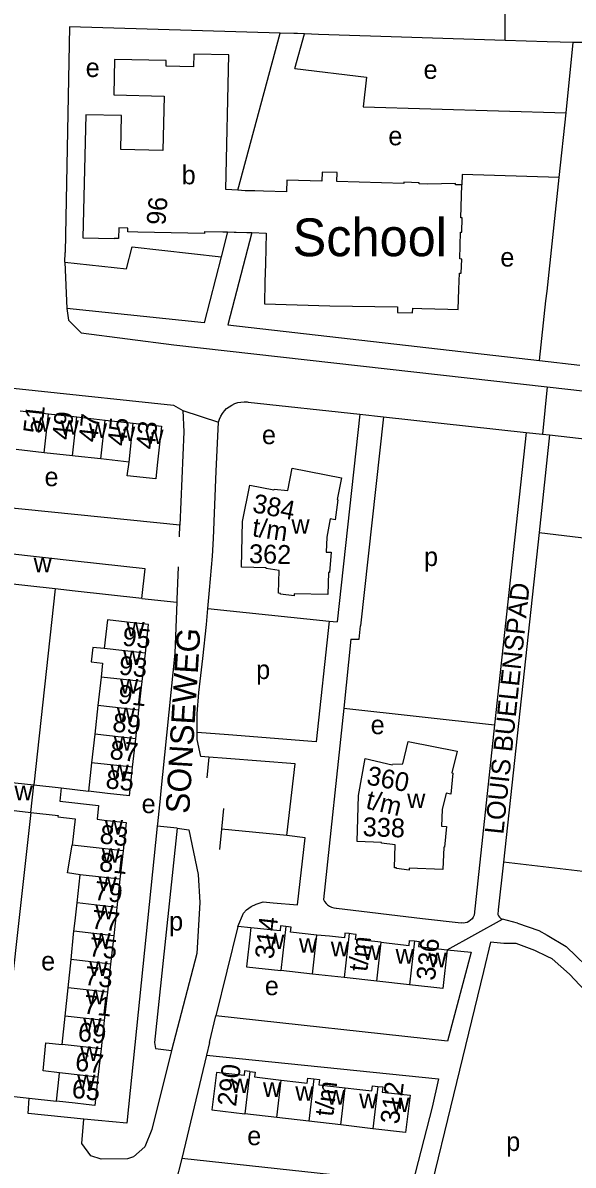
# Model space of a CAD drawing. Extents: x 161936 to 163647, y 386450 to 388633.
# Drawn here: x 162488.9 to 162605.5, y 387951 to 388193.1 of the extents above; entities that cross this region are included whole.
import ezdxf

# ---------------------------------------------------------------- set-up
doc = ezdxf.new("R2010")
doc.units = 0
for name, color, linetype in [('BLT_Basislijn', 7, 'Continuous'), ('BLT_Bebouwing', 7, 'Continuous'), ('BLT_Bebouwing_beschrifting', 7, 'Continuous'), ('BLT_Centroide', 7, 'Continuous'), ('BLT_Huisnummer', 7, 'Continuous'), ('BLT_Huisnummer_ tussenligend', 7, 'Continuous'), ('BLT_Huisnummer_reeks', 7, 'Continuous'), ('BLT_Onderverdeling_panden', 7, 'Continuous'), ('BLT_Straatnaam', 7, 'Continuous'), ('BLT_Straatnaam_verkleind', 7, 'Continuous'), ('BLT_Vlakafsluiter', 7, 'Continuous')]:
    doc.layers.add(name, color=color, linetype=linetype)

msp = doc.modelspace()

# ---------------------------------------------------------------- linework, layer by layer
at = {"layer": 'BLT_Basislijn'}
for p, q in [((162591.14, 388189.38), (162591.12, 388195.74)), ((162534.5, 388157.64), (162543.44, 388190.92)), ((162546.6, 388183.4), (162548.58, 388190.76)), ((162609.32, 388188.96), (162605.52, 388188.92)), ((162497.85, 388142.38), (162497.93, 388144.44)), ((162497.85, 388142.38), (162498.24, 388132.55)), ((162598.44, 388121.53), (162599.78, 388134.16)), ((162598.44, 388121.53), (162606.98, 388120.56)), ((162536.69, 388112.74), (162560.36, 388110.16)), ((162560.36, 388110.16), (162555.53, 388066.15)), ((162560.36, 388110.16), (162565.33, 388109.61)), ((162565.33, 388109.61), (162560.46, 388065.31)), ((162565.33, 388109.61), (162595.57, 388106.3)), ((162595.57, 388106.3), (162588.88, 388044.33)), ((162595.57, 388106.3), (162599.03, 388105.93)), ((162600.54, 388105.76), (162598.32, 388085.1)), ((162599.03, 388105.93), (162600.54, 388105.76)), ((162600.54, 388105.76), (162636.56, 388101.7)), ((162522.13, 388084.21), (162522.22, 388086.64)), ((162598.32, 388085.1), (162590.77, 388015.27)), ((162495.79, 388073.14), (162491.26, 388031.64)), ((162514.13, 388071.09), (162521.54, 388070.34)), ((162528.14, 388069), (162553.83, 388066.33)), ((162553.83, 388066.33), (162551.1, 388040.74)), ((162553.83, 388066.33), (162555.53, 388066.15)), ((162558.46, 388062.52), (162556.92, 388047.89)), ((162556.92, 388047.89), (162552.66, 388007.31)), ((162556.92, 388047.89), (162588.88, 388044.33)), ((162588.88, 388044.33), (162584.53, 388003.99)), ((162497.05, 388030.99), (162502.82, 388030.26)), ((162490.61, 388025.79), (162483.95, 387965.94)), ((162521.63, 388022.41), (162517.4, 388022.89)), ((162590.77, 388015.27), (162589.68, 388005.16)), ((162593.73, 388002.33), (162590.59, 388003.13)), ((162534.52, 388001.6), (162529.82, 387982.7)), ((162537.22, 388001.34), (162534.52, 388001.6)), ((162528.49, 387976.99), (162529.82, 387982.7)), ((162528.49, 387976.99), (162527.86, 387974.33)), ((162527.86, 387974.33), (162522.59, 387952.41)), ((162483.95, 387965.94), (162490.26, 387965.22)), ((162490.26, 387965.22), (162496.06, 387964.57)), ((162522.59, 387952.41), (162521.25, 387947.22))]:
    msp.add_line(p, q, dxfattribs=at)
for points in [[(162543.44, 388190.92), (162498.79, 388192.23), (162497.93, 388144.44)], [(162546.33, 388190.83), (162543.44, 388190.92)], [(162548.58, 388190.76), (162547.12, 388190.81), (162546.33, 388190.83)], [(162591.14, 388189.38), (162551.58, 388190.66), (162548.58, 388190.76)], [(162605.52, 388188.92), (162600, 388189.1), (162591.14, 388189.38)], [(162604.07, 388174.05), (162605.52, 388188.92)], [(162546.6, 388183.4), (162561.76, 388181.57), (162561.03, 388175.31), (162604.07, 388174.05)], [(162602.6, 388160.36), (162604.07, 388174.05)], [(162602.6, 388160.36), (162581.99, 388160.96), (162581.93, 388158.74)], [(162599.78, 388134.16), (162600, 388136.23), (162602.6, 388160.36)], [(162532.32, 388148.78), (162530.96, 388143.54)], [(162537.45, 388148.64), (162532.37, 388129.08)], [(162497.85, 388142.38), (162510.93, 388140.97), (162512.07, 388145.61), (162530.96, 388143.54)], [(162530.96, 388143.54), (162527.32, 388129.53)], [(162498.24, 388132.55), (162498.63, 388130.09), (162501.31, 388127.39), (162520.91, 388124.84), (162600, 388115.94)], [(162527.32, 388129.53), (162498.24, 388132.55)], [(162532.37, 388129.08), (162598.44, 388121.53)], [(162462.15, 388118.33), (162520.89, 388112.08), (162522.8, 388110.92)], [(162600, 388115.94), (162638.7, 388111.58), (162641.05, 388111.51), (162643.08, 388111.89), (162644.73, 388113.96), (162645.02, 388116.24)], [(162522.8, 388110.92), (162523.03, 388106.43), (162522.22, 388086.64)], [(162530.39, 388108.48), (162530.59, 388109.13), (162530.87, 388109.74), (162531.22, 388110.32), (162531.64, 388110.86), (162532.12, 388111.34), (162532.65, 388111.76), (162533.22, 388112.11), (162533.84, 388112.4), (162534.48, 388112.61), (162535.15, 388112.74), (162535.82, 388112.79), (162536.49, 388112.77), (162536.69, 388112.74)], [(162529.36, 388083.81), (162529.88, 388098.09), (162530.39, 388108.48)], [(162593.73, 388002.33), (162598.24, 388000.78), (162600, 387999.74), (162604.06, 387997.34), (162622.92, 387979.16), (162624.11, 387982.32), (162636.56, 388101.7)], [(162522.22, 388086.64), (162472.61, 388091.7), (162471.95, 388091.77)], [(162598.32, 388085.1), (162629.52, 388081.37), (162622.01, 388011.53), (162590.77, 388015.27)], [(162528.14, 388069), (162528.49, 388072.86), (162529.09, 388080.1), (162529.36, 388083.81)], [(162521.84, 388077.85), (162521.56, 388070.88), (162521.54, 388070.34)], [(162521.54, 388070.34), (162521.12, 388059.5), (162518.13, 388029.66), (162518.03, 388028.71)], [(162525.88, 388042.72), (162525.85, 388046.69), (162526.23, 388051.18), (162527.07, 388058.4), (162527.82, 388065.62), (162528.14, 388069)], [(162558.46, 388062.52), (162560.19, 388062.52), (162560.46, 388065.31)], [(162528.36, 388037.51), (162526.64, 388037.64), (162525.89, 388041.25), (162525.88, 388042.72)], [(162551.1, 388040.74), (162532.51, 388042.2), (162525.88, 388042.72)], [(162528.36, 388037.51), (162527.92, 388033.09)], [(162546.62, 388036.08), (162532.12, 388037.21), (162528.36, 388037.51)], [(162544.87, 388020.86), (162546.62, 388036.08)], [(162518.03, 388028.71), (162517.45, 388023.38), (162517.4, 388022.89)], [(162531.45, 388026.6), (162531.45, 388026.6), (162531.01, 388022.26)], [(162517.4, 388022.89), (162510.98, 387959.96), (162501.87, 387960.77)], [(162521.63, 388022.41), (162516.82, 387977.05), (162517.01, 387975.72), (162520.43, 387975.31)], [(162521.63, 388022.41), (162524.1, 388022.12), (162526.09, 388012.62), (162526.46, 388006.67), (162525.82, 387995.91), (162520.43, 387975.31)], [(162531.01, 388022.26), (162531.01, 388022.26), (162530.57, 388017.92)], [(162544.87, 388020.86), (162531.01, 388022.26)], [(162534.52, 388001.6), (162535.67, 388004.45), (162536.33, 388005.15), (162537.3, 388005.83), (162538.35, 388006.33), (162539.88, 388006.81), (162541.95, 388006.65), (162547.15, 388006.18), (162548.78, 388020.41), (162544.87, 388020.86)], [(162552.66, 388007.31), (162552.88, 388006.88), (162553.17, 388006.49), (162553.52, 388006.16), (162553.91, 388005.89), (162554.35, 388005.69), (162554.82, 388005.56), (162555.3, 388005.51), (162555.42, 388005.51)], [(162555.42, 388005.51), (162573.64, 388003.3), (162581.82, 388002.36)], [(162589.68, 388005.16), (162589.6, 388004.16), (162589.72, 388003.84), (162589.92, 388003.56), (162590.18, 388003.33), (162590.48, 388003.17), (162590.59, 388003.13)], [(162584.53, 388003.99), (162584.36, 388003.59), (162584.11, 388003.22), (162583.81, 388002.91), (162583.45, 388002.65), (162583.06, 388002.47), (162582.63, 388002.36), (162582.2, 388002.33), (162581.82, 388002.36)], [(162611.3, 387984.51), (162604.76, 387991.48), (162601.11, 387994.73), (162600, 387995.27), (162597.43, 387996.52), (162593.47, 387997.98), (162590.82, 387998), (162588.04, 387998.3), (162586.55, 387992.05), (162568.7, 387918.58), (162570.36, 387917.56), (162582.35, 387916.2)], [(162578.86, 387996.68), (162583.95, 387996.15), (162578.89, 387977.33), (162529.82, 387982.7)], [(162520.43, 387975.31), (162516.27, 387958.56), (162514.77, 387954.9), (162512.39, 387952.82), (162511.11, 387952.37), (162505.55, 387952.28), (162503.36, 387952.99), (162501.46, 387955.63), (162501.87, 387960.77)], [(162527.86, 387974.33), (162577.03, 387969.3), (162575.69, 387963.35), (162571.53, 387947.14), (162522.59, 387952.41)], [(162501.87, 387960.77), (162490.05, 387961.96), (162490.26, 387965.22)]]:
    msp.add_lwpolyline(points, dxfattribs=at)
at = {"layer": 'BLT_Bebouwing'}
for p, q in [((162488.4, 388110.9), (162494.38, 388110.24)), ((162494.38, 388110.24), (162500.37, 388109.59)), ((162500.37, 388109.59), (162506.36, 388108.93)), ((162506.36, 388108.93), (162512.34, 388108.27)), ((162493.48, 388102), (162487.49, 388102.66)), ((162499.46, 388101.34), (162493.48, 388102)), ((162511.43, 388100.02), (162505.45, 388100.68)), ((162495.79, 388073.14), (162470.29, 388075.98)), ((162514.21, 388053.5), (162514.89, 388059.55)), ((162505.51, 388054.47), (162504.84, 388048.42)), ((162513.54, 388047.45), (162514.21, 388053.5)), ((162504.84, 388048.42), (162504.17, 388042.36)), ((162512.87, 388041.4), (162513.54, 388047.45)), ((162504.17, 388042.36), (162503.5, 388036.31)), ((162512.2, 388035.35), (162512.87, 388041.4)), ((162503.5, 388036.31), (162502.82, 388030.26)), ((162511.52, 388029.29), (162512.2, 388035.35)), ((162510.85, 388023.64), (162510.18, 388017.65)), ((162510.18, 388017.65), (162509.52, 388011.65)), ((162500.42, 388006.59), (162501.09, 388012.58)), ((162509.52, 388011.65), (162508.85, 388005.65)), ((162508.85, 388005.65), (162508.18, 387999.65)), ((162508.18, 387999.65), (162507.52, 387993.65)), ((162498.52, 387988.58), (162499.14, 387994.59)), ((162507.52, 387993.65), (162506.85, 387987.66)), ((162550.33, 387991.52), (162543.63, 387992.26)), ((162557.02, 387990.78), (162550.33, 387991.52)), ((162563.94, 387990.01), (162557.02, 387990.78)), ((162570.86, 387989.24), (162563.94, 387990.01)), ((162497.91, 387982.58), (162498.52, 387988.58)), ((162506.85, 387987.66), (162506.19, 387981.66)), ((162497.29, 387976.57), (162497.91, 387982.58)), ((162506.19, 387981.66), (162505.52, 387975.66)), ((162505.52, 387975.66), (162504.85, 387969.66)), ((162542.74, 387961.13), (162535.98, 387961.93)), ((162549.51, 387960.34), (162542.74, 387961.13)), ((162556.29, 387959.54), (162549.51, 387960.34)), ((162563.06, 387958.75), (162556.29, 387959.54))]:
    msp.add_line(p, q, dxfattribs=at)
for points in [[(162531.94, 388157.81), (162532.58, 388186.29), (162525.15, 388186.46), (162525.09, 388183.78), (162519.28, 388183.91), (162519.31, 388185.1), (162508.38, 388185.35), (162508.21, 388177.83), (162518.88, 388177.59), (162518.62, 388166.05), (162509.68, 388166.25), (162509.84, 388173.45), (162502.25, 388173.62), (162501.66, 388147.55), (162508.26, 388147.4)], [(162574.69, 388158.92), (162572.91, 388158.96), (162572.92, 388159.22), (162569.69, 388159.31), (162569.68, 388159.05), (162555.49, 388159.45), (162555.54, 388161.35), (162552.33, 388161.44), (162552.29, 388159.54), (162544.9, 388159.76), (162544.83, 388157.27), (162539.9, 388157.42)], [(162534.5, 388157.64), (162531.94, 388157.81)], [(162536.03, 388157.53), (162534.5, 388157.64)], [(162536.41, 388157.52), (162536.03, 388157.53)], [(162538.11, 388157.47), (162536.41, 388157.52)], [(162539.9, 388157.42), (162538.11, 388157.47)], [(162581.93, 388158.74), (162580.6, 388158.77), (162580.61, 388159.03), (162574.69, 388158.92)], [(162581.92, 388143.05), (162581.51, 388143.07), (162581.65, 388148.74), (162581.93, 388148.74), (162582, 388151.75), (162581.75, 388151.76), (162581.93, 388158.74)], [(162513.32, 388148.77), (162511.19, 388148.82), (162511.21, 388149.62), (162509.26, 388149.67), (162509.21, 388147.38), (162508.26, 388147.4)], [(162527.41, 388148.91), (162527.4, 388148.45), (162513.32, 388148.77)], [(162527.41, 388148.91), (162531.29, 388148.81)], [(162531.29, 388148.81), (162532.32, 388148.78)], [(162532.32, 388148.78), (162533.74, 388148.74)], [(162533.74, 388148.74), (162534.1, 388148.73), (162536.42, 388148.67)], [(162536.42, 388148.67), (162537.45, 388148.64)], [(162537.45, 388148.64), (162540.52, 388148.55), (162540.35, 388142.04), (162540.24, 388138.22)], [(162581.33, 388136.67), (162581.43, 388140.04), (162581.84, 388140.03), (162581.92, 388143.05)], [(162540.24, 388138.22), (162540.11, 388133.52), (162553.99, 388133.12), (162568.33, 388132.89), (162568.31, 388131.73), (162571.53, 388131.63), (162571.56, 388132.63), (162573.46, 388132.59), (162578.96, 388132.43), (162581.2, 388132.38), (162581.33, 388136.67)], [(162512.34, 388108.27), (162518.32, 388107.61), (162517.42, 388099.37), (162517.1, 388096.46)], [(162505.45, 388100.68), (162500, 388101.28), (162499.46, 388101.34)], [(162517.1, 388096.46), (162511.02, 388097.12), (162511.43, 388100.02)], [(162537.01, 388095.12), (162542.14, 388094.11), (162542.18, 388094.3), (162545.07, 388093.97), (162546, 388098.71), (162556.42, 388096.67)], [(162556.42, 388096.67), (162555.52, 388092.07), (162555.7, 388092.04), (162555.08, 388087.76), (162554.07, 388087.96), (162553.32, 388084.11), (162553.21, 388080.93), (162554.24, 388080.9), (162553.89, 388076.6), (162553.7, 388076.6), (162553.58, 388071.95)], [(162535.27, 388077.75), (162535.51, 388087.43), (162537.01, 388095.12)], [(162514.13, 388071.09), (162514.83, 388077.37), (162500, 388079.02), (162470.99, 388082.26)], [(162553.58, 388071.95), (162546.45, 388072.13), (162546.44, 388071.71), (162543.56, 388072.01), (162543.56, 388072.2), (162543.11, 388072.21), (162543.23, 388077.03), (162540.49, 388077.45), (162540.49, 388077.62), (162535.27, 388077.75)], [(162514.13, 388071.09), (162500, 388072.67), (162495.79, 388073.14)], [(162515.56, 388065.6), (162511.02, 388066.11), (162506.86, 388066.57), (162506.19, 388060.52)], [(162514.89, 388059.55), (162515.56, 388065.6)], [(162506.19, 388060.52), (162503.77, 388060.71), (162503.43, 388057.67), (162505.84, 388057.4), (162505.51, 388054.47)], [(162561.5, 388037.21), (162567.21, 388035.84), (162567.25, 388036.02), (162569.46, 388036.09), (162570.59, 388040.78), (162580.97, 388038.78)], [(162580.97, 388038.78), (162579.86, 388034.16), (162580.04, 388034.12), (162579.62, 388029.62), (162578.62, 388029.86), (162577.79, 388026.38), (162577.66, 388022.83), (162578.69, 388022.79), (162578.31, 388018.42), (162578.12, 388018.43), (162577.95, 388013.7), (162570.82, 388013.95), (162570.81, 388013.52), (162568.11, 388013.86), (162568.11, 388014.05), (162567.67, 388014.06)], [(162559.74, 388019.62), (162560.09, 388029.37), (162561.5, 388037.21)], [(162485.34, 388032.29), (162491.26, 388031.64)], [(162491.26, 388031.64), (162497.05, 388030.99)], [(162497.05, 388030.99), (162496.74, 388028.15), (162505, 388027.23), (162504.68, 388024.32)], [(162511.52, 388029.29), (162506.85, 388029.81), (162502.82, 388030.26)], [(162484.69, 388026.45), (162490.61, 388025.79)], [(162490.61, 388025.79), (162496.4, 388025.15), (162496.37, 388024.85), (162499.99, 388024.45), (162499.37, 388018.85)], [(162504.68, 388024.32), (162506.19, 388024.15), (162510.85, 388023.64)], [(162501.09, 388012.58), (162498.42, 388012.96), (162499.37, 388018.85)], [(162567.67, 388014.06), (162567.84, 388018.88), (162564.94, 388019.25), (162564.94, 388019.43), (162559.74, 388019.62)], [(162499.76, 388000.59), (162500, 388002.79), (162500.42, 388006.59)], [(162499.14, 387994.59), (162499.69, 388000), (162499.76, 388000.59)], [(162537.22, 388001.34), (162537.17, 388000.81), (162537.08, 388000), (162536.31, 387993.08), (162543.63, 387992.26)], [(162544.67, 388001.6), (162543.55, 388001.73), (162543.43, 388000.65), (162537.22, 388001.34)], [(162551.25, 387999.8), (162545.67, 388000.4), (162545.79, 388001.48), (162544.67, 388001.6)], [(162558.06, 388000.1), (162557.17, 388000.2), (162557.15, 388000), (162557.06, 387999.17), (162553.92, 387999.52), (162551.25, 387999.8)], [(162564.86, 387998.25), (162559.43, 387998.84), (162559.55, 387999.93), (162558.95, 388000), (162558.06, 388000.1)], [(162564.86, 387998.25), (162566.52, 387998.07), (162570.76, 387997.6), (162570.87, 387998.65), (162571.89, 387998.53)], [(162571.89, 387998.53), (162572.91, 387998.42), (162572.79, 387997.35), (162578.86, 387996.68)], [(162578.86, 387996.68), (162577.95, 387988.45), (162570.86, 387989.24)], [(162496.68, 387970.57), (162493.21, 387970.99), (162493.82, 387976.92), (162497.29, 387976.57)], [(162496.06, 387964.57), (162496.6, 387969.81), (162496.68, 387970.57)], [(162529.94, 387970.69), (162529, 387962.75)], [(162537.03, 387970.86), (162535.93, 387970.99), (162535.81, 387970), (162529.94, 387970.69)], [(162537.03, 387970.86), (162538.13, 387970.73), (162538.01, 387969.75), (162543.67, 387969.06)], [(162504.85, 387969.66), (162504.19, 387963.66), (162502.33, 387963.87), (162500, 387964.13), (162496.06, 387964.57)], [(162543.67, 387969.06), (162547.39, 387968.61), (162549.2, 387968.4), (162549.33, 387969.45), (162550.56, 387969.3)], [(162550.56, 387969.3), (162551.79, 387969.16), (162551.66, 387968.03), (162557.21, 387967.41)], [(162557.21, 387967.41), (162559.69, 387967.13), (162562.89, 387966.76), (162563.02, 387967.84), (162564.12, 387967.72)], [(162564.12, 387967.72), (162565.22, 387967.59), (162565.09, 387966.52), (162570.97, 387965.83), (162570.04, 387957.93), (162563.06, 387958.75)], [(162529, 387962.75), (162535.98, 387961.93)]]:
    msp.add_lwpolyline(points, dxfattribs=at)
at = {"layer": 'BLT_Onderverdeling_panden'}
for p, q in [((162493.48, 388102), (162494.38, 388110.24)), ((162499.46, 388101.34), (162500.37, 388109.59)), ((162505.45, 388100.68), (162506.36, 388108.93)), ((162511.43, 388100.02), (162512.34, 388108.27)), ((162514.89, 388059.55), (162506.19, 388060.52)), ((162514.21, 388053.5), (162505.51, 388054.47)), ((162513.54, 388047.45), (162504.84, 388048.42)), ((162512.87, 388041.4), (162504.17, 388042.36)), ((162512.2, 388035.35), (162503.5, 388036.31)), ((162490.61, 388025.79), (162491.26, 388031.64)), ((162510.18, 388017.65), (162499.37, 388018.85)), ((162509.52, 388011.65), (162501.09, 388012.58)), ((162508.85, 388005.65), (162500.42, 388006.59)), ((162508.18, 387999.65), (162499.76, 388000.59)), ((162544.67, 388001.6), (162543.63, 387992.26)), ((162550.33, 387991.52), (162551.25, 387999.8)), ((162558.06, 388000.1), (162557.02, 387990.78)), ((162563.94, 387990.01), (162564.86, 387998.25)), ((162571.89, 387998.53), (162570.86, 387989.24)), ((162507.52, 387993.65), (162499.14, 387994.59)), ((162506.85, 387987.66), (162498.52, 387988.58)), ((162506.19, 387981.66), (162497.91, 387982.58)), ((162505.52, 387975.66), (162497.29, 387976.57)), ((162504.85, 387969.66), (162496.68, 387970.57)), ((162537.03, 387970.86), (162535.98, 387961.93)), ((162542.74, 387961.13), (162543.67, 387969.06)), ((162550.56, 387969.3), (162549.51, 387960.34)), ((162556.29, 387959.54), (162557.21, 387967.41)), ((162564.12, 387967.72), (162563.06, 387958.75))]:
    msp.add_line(p, q, dxfattribs=at)
at = {"layer": 'BLT_Vlakafsluiter'}
for p, q in [((162600, 388115.94), (162599.03, 388105.93)), ((162522.8, 388110.92), (162530.39, 388108.48)), ((162578.86, 387996.68), (162590.59, 388003.13))]:
    msp.add_line(p, q, dxfattribs=at)

# ---------------------------------------------------------------- texts
at = {"layer": 'BLT_Bebouwing_beschrifting'}
msp.add_text('School', height=8, dxfattribs=at).set_placement((162546.09, 388143.65))
at = {"layer": 'BLT_Centroide'}
for s, p in [('e', (162502.25, 388181.62)), ('e', (162573.84, 388181.22)), ('e', (162566.38, 388167.15)), ('b', (162522.59, 388158.88)), ('e', (162590.11, 388141.45)), ('w', (162490.94, 388106.45)), ('w', (162496.92, 388105.8)), ('w', (162502.91, 388105.14)), ('w', (162508.89, 388104.48)), ('w', (162514.88, 388103.83)), ('e', (162539.6, 388103.82)), ('e', (162493.53, 388094.91)), ('w', (162545.84, 388084.84)), ('w', (162491.22, 388076.69)), ('p', (162573.94, 388077.99)), ('w', (162510.88, 388063.06)), ('w', (162510.2, 388057)), ('p', (162538.37, 388054.04)), ('w', (162509.53, 388050.97)), ('w', (162508.86, 388044.91)), ('e', (162562.63, 388042.36)), ('w', (162508.19, 388038.84)), ('w', (162507.52, 388032.81)), ('w', (162487.17, 388028.35)), ('e', (162514.1, 388025.62)), ('w', (162570.36, 388026.7)), ('w', (162506.3, 388021.09)), ('w', (162505.64, 388015.12)), ('w', (162504.97, 388009.12)), ('w', (162504.3, 388003.12)), ('p', (162519.93, 388000.73)), ('w', (162503.65, 387997.12)), ('w', (162540.48, 387996.8)), ('w', (162547.44, 387996.03)), ('w', (162554.19, 387995.3)), ('w', (162560.94, 387994.52)), ('e', (162492.81, 387992.3)), ('w', (162567.92, 387993.73)), ('w', (162574.86, 387992.95)), ('w', (162503.01, 387991.12)), ('e', (162540.21, 387987.04)), ('w', (162502.38, 387985.12)), ('w', (162501.73, 387979.12)), ('w', (162501.09, 387973.12)), ('w', (162500.45, 387967.12)), ('w', (162533.02, 387966.3)), ('w', (162539.83, 387965.5)), ('w', (162546.66, 387964.69)), ('w', (162553.36, 387963.86)), ('w', (162560.2, 387963.08)), ('w', (162567.02, 387962.28)), ('e', (162536.48, 387955.26)), ('p', (162591.35, 387954.03))]:
    msp.add_text(s, height=4, dxfattribs=at).set_placement(p)
at = {"layer": 'BLT_Huisnummer'}
for s, rotation, p in [('96', 84.9075, (162519.11, 388150.12)), ('51', 83.7277, (162492.97, 388105.92)), ('47', 83.727, (162504.69, 388104.11)), ('43', 83.7322, (162516.83, 388102.58)), ('95', 353.6533, (162509.89, 388061.16)), ('89', 353.6591, (162507.79, 388042.93)), ('85', 353.6582, (162506.35, 388030.92)), ('83', 353.6598, (162505.09, 388019.24)), ('77', 353.6598, (162503.31, 388001.18)), ('73', 353.6576, (162501.85, 387989.25)), ('69', 353.6606, (162500.46, 387977.39)), ('65', 353.6493, (162499.17, 387965.33))]:
    msp.add_text(s, height=4, rotation=rotation, dxfattribs=at).set_placement(p)
at = {"layer": 'BLT_Huisnummer_ tussenligend'}
for s, rotation, p in [('49', 83.727, (162499.06, 388104.59)), ('45', 83.7322, (162510.8, 388103.31)), ('93', 353.6591, (162509.14, 388055.03)), ('91', 353.6591, (162508.98, 388048.93)), ('87', 353.6582, (162507.21, 388037.11)), ('81', 353.6598, (162504.98, 388013.35)), ('79', 353.6598, (162503.92, 388007.29)), ('75', 353.6576, (162502.79, 387995.36)), ('71', 353.6606, (162501.65, 387983.18)), ('67', 353.6493, (162499.89, 387971.1))]:
    msp.add_text(s, height=4, rotation=rotation, dxfattribs=at).set_placement(p)
at = {"layer": 'BLT_Huisnummer_reeks'}
for s, rotation, p in [('384', 348.9324, (162537.41, 388089.43)), ('t/m', 351.3732, (162537.38, 388084.32)), ('362', 358.5773, (162536.82, 388078.62)), ('360', 349.1057, (162561.57, 388031.75)), ('t/m', 346.5202, (162561.41, 388026.68)), ('338', 357.9583, (162560.9, 388020.77)), ('314', 83.6699, (162542.05, 387994.58)), ('t/m', 83.6537, (162561.91, 387991.93)), ('336', 83.6613, (162576.24, 387990.02)), ('290', 83.3088, (162534.1, 387963.33)), ('t/m', 83.2995, (162554.69, 387961.22)), ('312', 83.2986, (162568.63, 387959.59))]:
    msp.add_text(s, height=4, rotation=rotation, dxfattribs=at).set_placement(p)
at = {"layer": 'BLT_Straatnaam'}
msp.add_text('SONSEWEG', height=5, rotation=86.4853, dxfattribs=at).set_placement((162524.17, 388025.41))
at = {"layer": 'BLT_Straatnaam_verkleind'}
msp.add_text('LOUIS BUELENSPAD', height=4, rotation=83.9699, dxfattribs=at).set_placement((162590.74, 388021.02))

doc.saveas('drawing.dxf')
